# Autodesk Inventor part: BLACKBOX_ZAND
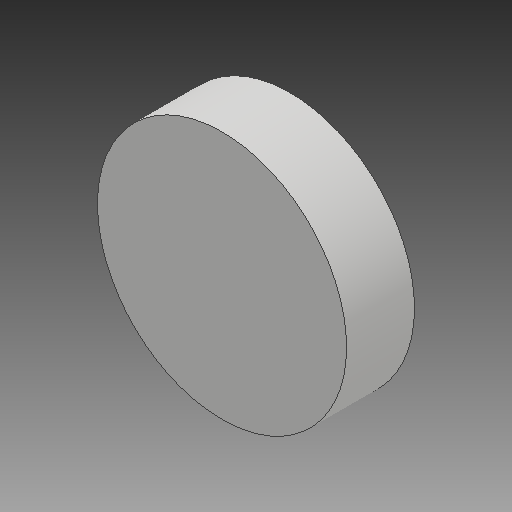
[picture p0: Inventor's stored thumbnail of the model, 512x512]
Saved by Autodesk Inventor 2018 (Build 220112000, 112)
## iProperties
Created: 2019-01
Part Number: BLACKBOX_ZAND
Material: Generisch
Document SubType Name: Modeling
Designer: zand
Density: 1 g/cm^3
Appearance: Vorgabe
Author: zand
Revision Number: 2LAST_VERSION
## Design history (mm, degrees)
feature "Basis1"
node "Volumenkörper1"
